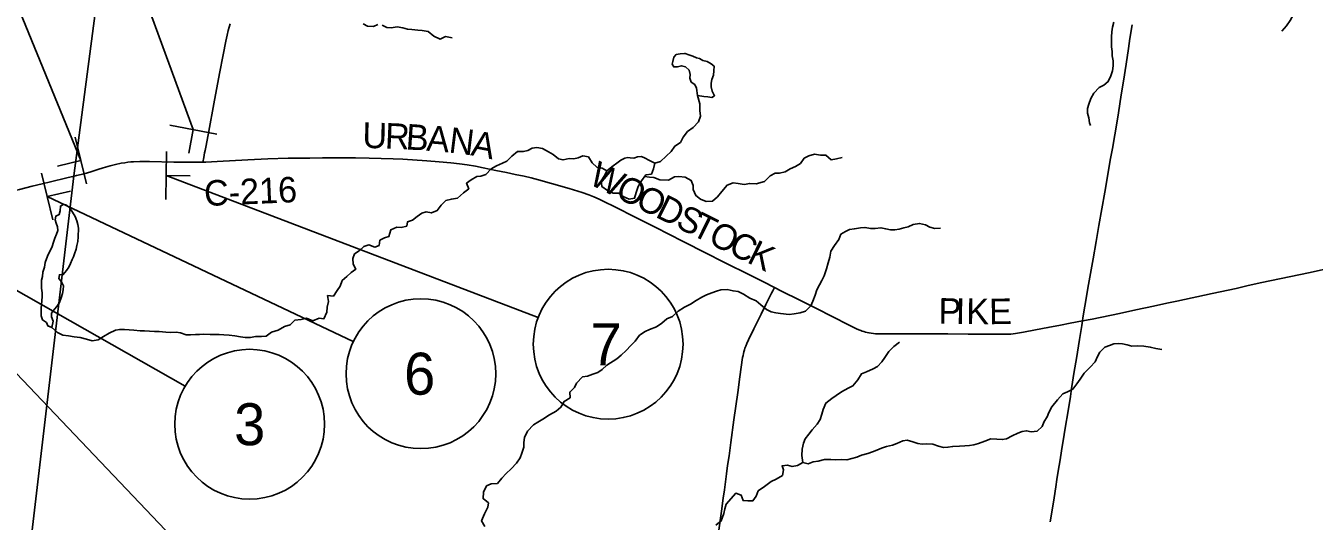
# Model space of a CAD drawing. Extents: x 0 to 1101, y 0 to 440.
# Drawn here: x 356 to 442.1, y 68.6 to 101.7 of the extents above; entities that cross this region are included whole.
import ezdxf

# ---------------------------------------------------------------- set-up
doc = ezdxf.new("R2010")
doc.units = 0
for name, color, linetype in [('Default', 7, 'Continuous'), ('GM_X_County_Road', 7, 'Continuous'), ('GM_X_County_Road_Text', 7, 'Continuous'), ('GM_X_Minor_Lake', 7, 'Continuous'), ('GM_X_Minor_River', 7, 'Continuous'), ('GM_X_State_Location', 7, 'Continuous'), ('GM_X_State_Route', 7, 'Continuous'), ('GM_X_Township', 7, 'Continuous'), ('GM_X_Township_Road', 7, 'Continuous'), ('SH_Masking', 7, 'Continuous'), ('SH_Text', 7, 'Continuous'), ('SN_P_Signs', 7, 'Continuous')]:
    doc.layers.add(name, color=color, linetype=linetype)

msp = doc.modelspace()

# ---------------------------------------------------------------- linework, layer by layer
at = {"layer": 'Default'}
for points in [[(359.263, 91.656), (359.423, 91.693), (359.929, 91.816), (360.377, 91.94), (360.855, 92.095), (361.209, 92.212), (361.673, 92.353), (362.037, 92.443), (362.397, 92.514), (362.644, 92.554), (362.858, 92.582), (363.048, 92.6), (363.239, 92.614), (363.651, 92.629), (364.304, 92.627), (365.926, 92.598), (366.491, 92.587), (367.01, 92.585), (367.558, 92.583), (367.857, 92.588), (367.921, 92.899), (367.983, 93.215), (368.013, 93.362), (368.073, 93.695), (368.259, 94.665), (368.597, 96.479), (368.976, 98.513), (369.211, 99.759), (369.393, 100.674), (369.483, 101.075), (369.562, 101.382), (369.689, 101.824)], [(348.965, 89.153), (349.336, 89.261), (349.645, 89.344), (350.108, 89.45), (350.608, 89.565), (350.951, 89.644), (351.412, 89.756), (352.146, 89.933), (353.305, 90.216), (353.598, 90.289), (354.275, 90.452), (355.059, 90.64), (355.621, 90.771), (356.471, 90.987), (357.142, 91.149), (357.681, 91.279), (358.77, 91.542), (359.263, 91.656)]]:
    msp.add_lwpolyline(points, dxfattribs=at)
at = {"layer": 'GM_X_County_Road'}
for points in [[(426.602, 81.99), (426.628, 82.176), (426.716, 82.735), (426.8, 83.23), (426.967, 84.185), (427.311, 86.131), (427.513, 87.288), (427.701, 88.371), (428.085, 90.594), (428.172, 91.089), (428.459, 92.722), (428.594, 93.511), (428.759, 94.409), (428.891, 95.2), (428.998, 95.882), (429.188, 97.077), (429.332, 97.997), (429.508, 99.139), (429.666, 100.17), (429.772, 100.852), (429.909, 101.754)], [(367.857, 92.588), (368.063, 92.598), (368.82, 92.635), (370.863, 92.744), (372.201, 92.8), (373.56, 92.852), (374.119, 92.856), (375.013, 92.863), (375.852, 92.872), (377.101, 92.881), (378.052, 92.877), (378.965, 92.86), (380.568, 92.818), (381.22, 92.785), (382.82, 92.68), (383.638, 92.617), (384.419, 92.549), (384.994, 92.486), (385.511, 92.411), (386.062, 92.313), (386.574, 92.211), (387.415, 92.042), (388.145, 91.889), (388.71, 91.774), (389.31, 91.644), (389.782, 91.532), (390.269, 91.405), (391.15, 91.163), (392.314, 90.825), (393.189, 90.561), (393.63, 90.406), (393.959, 90.272), (394.319, 90.115), (394.69, 89.942), (395.326, 89.628), (396.824, 88.874), (398.24, 88.162), (398.835, 87.856), (400.064, 87.23), (401.345, 86.584), (402.743, 85.88), (404.355, 85.063), (405.289, 84.599), (406.031, 84.223)], [(426.602, 81.99), (427.25, 82.119), (429.074, 82.497), (430.168, 82.735), (431.334, 82.983), (432.227, 83.174), (432.902, 83.317), (435.27, 83.828), (436.856, 84.166), (437.656, 84.346), (438.584, 84.551), (441.683, 85.208), (443.524, 85.604)], [(406.031, 84.223), (406.503, 83.985), (407.724, 83.385), (408.839, 82.822), (409.889, 82.296), (411.016, 81.718), (411.516, 81.47), (411.668, 81.402), (411.788, 81.353), (411.897, 81.312), (411.997, 81.279), (412.115, 81.244), (412.228, 81.217), (412.353, 81.189), (412.483, 81.168), (412.637, 81.146), (412.777, 81.134), (413.11, 81.12), (414.228, 81.121), (415.029, 81.124), (415.794, 81.13), (417.602, 81.123), (418.962, 81.116), (419.353, 81.113), (420.08, 81.107), (420.788, 81.099), (421.514, 81.102), (421.654, 81.108), (421.819, 81.118), (421.979, 81.132), (422.124, 81.15), (422.655, 81.24), (423.462, 81.39), (424.286, 81.543), (425.128, 81.705), (425.786, 81.835), (426.602, 81.99)], [(424.437, 68.587), (424.589, 69.506), (424.7, 70.187), (424.819, 70.922), (424.896, 71.4), (424.986, 71.971), (425.105, 72.725), (425.202, 73.332), (425.375, 74.418), (425.465, 74.97), (425.611, 75.853), (425.792, 76.937), (425.875, 77.472), (426.053, 78.613), (426.197, 79.477), (426.41, 80.745), (426.56, 81.691), (426.602, 81.99)]]:
    msp.add_lwpolyline(points, dxfattribs=at)
at = {"layer": 'GM_X_Minor_Lake'}
for points in [[(400.066, 99.831), (400.023, 99.843), (399.726, 99.813), (399.464, 99.771), (399.302, 99.591), (399.252, 99.318), (399.204, 99.136), (399.304, 98.941), (399.554, 98.949), (399.817, 99.026), (400.09, 98.954), (400.326, 98.723), (400.401, 98.448), (400.386, 98.198), (400.462, 97.935), (400.711, 97.772), (400.832, 97.52), (400.888, 97.03)], [(400.888, 97.03), (401.326, 96.978), (401.576, 96.94), (401.86, 96.914), (402.033, 97.025), (401.877, 97.323), (401.802, 97.609), (401.794, 97.86), (401.843, 98.11), (401.95, 98.393), (401.988, 98.678), (402.015, 98.985), (401.801, 99.159), (401.541, 99.299), (401.258, 99.382), (401.02, 99.499), (400.827, 99.547), (400.578, 99.653), (400.318, 99.759), (400.066, 99.831)], [(398.05, 92.522), (397.643, 92.721), (397.406, 92.861), (397.145, 92.967), (396.883, 92.948), (396.643, 92.86), (396.404, 92.886), (396.233, 92.899), (396.039, 92.856), (395.764, 92.712), (395.499, 92.511), (395.269, 92.343), (394.842, 92.007)], [(394.842, 92.007), (394.713, 91.712), (394.457, 91.351), (394.509, 90.963), (394.881, 90.707), (395.254, 90.52), (395.641, 90.526), (395.934, 90.306), (396.319, 90.13), (396.696, 90.182), (396.792, 90.556), (396.935, 90.965), (397.145, 91.349), (397.447, 91.744), (397.812, 91.784), (397.965, 92.136), (398.05, 92.522)], [(357.769, 81.562), (357.866, 81.982), (357.745, 82.257), (357.76, 82.519), (357.957, 82.767), (358.119, 82.947), (358.294, 83.218), (358.401, 83.536), (358.484, 83.819), (358.545, 84.069), (358.549, 84.331), (358.427, 84.595), (358.237, 84.825), (358.286, 85.075), (358.537, 85.083), (358.746, 85.365), (358.908, 85.591), (359.014, 85.817), (359.143, 86.089), (359.226, 86.281), (359.285, 86.474), (359.392, 86.78), (359.453, 87.018), (359.514, 87.302), (359.541, 87.598), (359.549, 88.19), (359.518, 88.419), (359.453, 88.67), (359.344, 88.956), (359.154, 89.255), (358.954, 89.554), (358.717, 89.751), (358.535, 89.765), (358.351, 89.654), (358.336, 89.346), (358.264, 89.085), (358.144, 89.034)], [(358.144, 89.034), (358.034, 88.986), (357.997, 88.747), (358.062, 88.519), (358.161, 88.267), (358.18, 88.027), (358.097, 87.778), (357.968, 87.506), (357.896, 87.256), (357.8, 86.962), (357.671, 86.667), (357.542, 86.418), (357.424, 86.147), (357.329, 85.886), (357.28, 85.59), (357.184, 85.25), (357.145, 84.966), (357.096, 84.704), (357.089, 84.169), (357.141, 83.872), (357.138, 83.622), (357.111, 83.337), (357.096, 83.087), (357.07, 82.848), (357.055, 82.609), (357.074, 82.335), (357.149, 82.061), (357.42, 81.897), (357.52, 81.657), (357.769, 81.562)]]:
    msp.add_lwpolyline(points, dxfattribs=at)
at = {"layer": 'GM_X_Minor_River'}
for points in [[(441.413, 103.145), (441.069, 102.842), (440.699, 102.437), (440.477, 102.053), (440.221, 101.681), (439.92, 101.343)], [(378.559, 101.817), (378.853, 101.665), (379.263, 101.636), (379.549, 101.769)], [(379.845, 101.742), (380.15, 101.567), (380.435, 101.564), (380.834, 101.615), (381.209, 101.553), (381.527, 101.469), (381.823, 101.454), (382.22, 101.403), (382.516, 101.376), (382.914, 101.303), (383.285, 100.99), (383.715, 100.802), (384.071, 100.968), (384.502, 100.894)], [(428.704, 101.929), (428.599, 101.61), (428.561, 101.29), (428.535, 100.947), (428.544, 100.581), (428.541, 100.284), (428.573, 99.986), (428.581, 99.689), (428.647, 99.345), (428.655, 99.025), (428.607, 98.682), (428.501, 98.34), (428.315, 97.965), (428.027, 97.727), (427.717, 97.57), (427.36, 97.185), (427.162, 96.844), (427.022, 96.468), (426.939, 96.16), (426.937, 95.862), (427.025, 95.541)], [(388.501, 92.992), (388.881, 93.306), (389.269, 93.301), (389.554, 93.365), (389.841, 93.521), (390.172, 93.562), (390.547, 93.511), (390.942, 93.278), (391.247, 93.092), (391.619, 92.813), (391.914, 92.741), (392.326, 92.827), (392.633, 92.8), (392.919, 92.876), (393.239, 93.008), (393.603, 92.935), (393.848, 92.533), (394.162, 92.255), (394.526, 92.182), (394.842, 92.007), (394.713, 91.712), (394.457, 91.351), (394.509, 90.963), (394.881, 90.707), (395.254, 90.52), (395.641, 90.526), (395.934, 90.306), (396.319, 90.13), (396.696, 90.182), (396.792, 90.556), (396.935, 90.965), (397.145, 91.349), (397.447, 91.744), (397.812, 91.784), (397.965, 92.136), (398.05, 92.522), (398.416, 92.642), (398.808, 92.979), (399.132, 93.293), (399.376, 93.666), (399.756, 93.911), (399.932, 94.262), (400.233, 94.646), (400.613, 94.902), (400.96, 95.285), (401.102, 95.659), (401.05, 96.047), (401.057, 96.48), (400.888, 97.03)], [(427.025, 95.541), (427.079, 95.221), (427.146, 95.037)], [(357.769, 81.562), (358.151, 81.215), (358.513, 81.039), (358.888, 80.988), (359.275, 80.937), (359.672, 80.886), (360.092, 80.766), (360.466, 80.659), (360.866, 80.722), (361.222, 80.956), (361.601, 81.167), (362.025, 81.366), (362.311, 81.431), (362.63, 81.426), (362.937, 81.399), (363.244, 81.372), (363.665, 81.332), (363.972, 81.328), (364.302, 81.312), (364.644, 81.296), (364.94, 81.292), (365.395, 81.24), (365.691, 81.225), (366.089, 81.231), (366.374, 81.204), (366.748, 81.074), (367.032, 81.058), (367.363, 81.077), (367.648, 81.095), (367.933, 81.103), (368.342, 81.086), (368.673, 81.093), (368.957, 81.078), (369.253, 81.062), (369.629, 81.034), (370.004, 80.995), (370.367, 80.933), (370.686, 80.883), (371.039, 80.89), (371.381, 80.953), (371.78, 80.948), (372.088, 80.966), (372.445, 81.246), (372.891, 81.366), (373.316, 81.611), (373.682, 81.742), (374.005, 82.034), (374.416, 82.097), (374.793, 82.183), (375.212, 82.006), (375.624, 82.172), (375.943, 82.133), (376.131, 82.575), (376.159, 82.905), (376.244, 83.28), (376.193, 83.679), (376.579, 83.651), (376.824, 84.013), (377.022, 84.306), (377.164, 84.68), (377.475, 84.949), (377.775, 85.219), (378.074, 85.443), (377.908, 85.787), (377.879, 86.152), (377.986, 86.469), (378.308, 86.67), (378.608, 86.962), (378.952, 87.06), (379.348, 86.918), (379.634, 87.028), (379.685, 87.38), (379.983, 87.536), (380.292, 87.634), (380.412, 88.066), (380.825, 88.254), (381.11, 88.239), (381.475, 88.325), (381.536, 88.609), (381.857, 88.707), (382.168, 88.965), (382.479, 89.188), (382.764, 89.276), (383.128, 89.202), (383.517, 89.357), (383.784, 89.718), (384.097, 90.032), (384.462, 90.13), (384.873, 90.193), (385.277, 90.541), (385.622, 90.809), (385.468, 91.176), (385.768, 91.4), (386.147, 91.634), (386.432, 91.664), (386.764, 91.774), (387.111, 92.134), (387.478, 92.345), (387.868, 92.522), (388.166, 92.655), (388.501, 92.992)], [(397.354, 91.622), (397.695, 91.581), (397.98, 91.566), (398.376, 91.401), (398.957, 91.393), (399.359, 91.615), (399.644, 91.634), (400.076, 91.583), (400.471, 91.373), (400.603, 91.04), (400.61, 90.755), (400.776, 90.354), (401.103, 90.122), (401.476, 89.958), (401.886, 89.975), (402.221, 90.267), (402.511, 90.639), (402.87, 91.044), (403.271, 91.209), (403.6, 91.171), (404.01, 91.108), (404.386, 91.172), (404.807, 91.143), (405.368, 91.295), (405.749, 91.666), (406.082, 91.855), (406.378, 91.862), (406.744, 91.949), (407.077, 92.149), (407.432, 92.293), (407.765, 92.493), (408.021, 92.854), (408.319, 93.01), (408.697, 93.13), (409.095, 93.056), (409.47, 93.051), (409.808, 92.739), (410.184, 92.814), (410.562, 92.9)], [(404.38, 83.515), (404.81, 83.327), (405.125, 83.06), (405.496, 82.759), (405.813, 82.606), (406.131, 82.522), (406.426, 82.484), (407.018, 82.431), (407.349, 82.472), (407.748, 82.535), (408.114, 82.644), (408.45, 83.004), (408.591, 83.321), (408.745, 83.718), (408.852, 84.069), (409.028, 84.398), (409.203, 84.691), (409.355, 84.997), (409.499, 85.462), (409.618, 85.86), (409.726, 86.257), (409.8, 86.655), (410.034, 87.028), (410.335, 87.434), (410.466, 87.774), (410.764, 87.963), (411.051, 88.085), (411.371, 88.149), (411.77, 88.212), (412.067, 88.231), (412.464, 88.157), (412.749, 88.153), (413.137, 88.216), (413.466, 88.132), (413.773, 88.082), (414.08, 88.078), (414.366, 88.12), (414.674, 88.195), (414.96, 88.283), (415.304, 88.426), (415.727, 88.5), (416.113, 88.415), (416.406, 88.252), (416.736, 88.167), (417.123, 88.185)], [(386.701, 68.268), (386.479, 68.658), (386.679, 69.111), (386.891, 69.564), (386.929, 69.849), (386.569, 70.139), (386.609, 70.56), (386.809, 70.979), (387.118, 71.111), (387.528, 71.14), (387.83, 71.5), (388.107, 71.816), (388.442, 72.119), (388.8, 72.49), (389.056, 72.851), (389.163, 73.157), (389.294, 73.577), (389.299, 73.873), (389.349, 74.215), (389.549, 74.645), (389.942, 75.061), (390.24, 75.228), (390.574, 75.429), (391.011, 75.73), (391.447, 75.964), (391.77, 76.233), (391.98, 76.618), (392.394, 76.863), (392.365, 77.239), (392.677, 77.543), (392.818, 77.837), (393.222, 78.253), (393.542, 78.306), (393.908, 78.449), (394.229, 78.559), (394.528, 78.76), (394.839, 79.029), (395.495, 79.453), (395.806, 79.711), (396.129, 80.026), (396.43, 80.352), (396.719, 80.644), (397.021, 81.039), (397.4, 81.296), (397.687, 81.429), (398.145, 81.605), (398.513, 81.839), (398.836, 82.131), (399.225, 82.297), (399.595, 82.634), (400.02, 82.901), (400.433, 83.112), (400.801, 83.347), (401.18, 83.581), (401.501, 83.725), (401.856, 83.868), (402.165, 83.989), (402.451, 84.076), (402.884, 84.082), (403.27, 83.997), (403.6, 83.958), (403.973, 83.782), (404.38, 83.515)], [(402.125, 68.366), (402.482, 68.646), (402.648, 69.146), (402.709, 69.441), (402.805, 69.759), (403.454, 70.502), (403.816, 70.372), (403.936, 70.006), (404.244, 69.99), (404.597, 69.985), (404.817, 70.29), (404.948, 70.642), (405.362, 70.932), (405.811, 71.279), (406.155, 71.423), (406.568, 71.679), (406.642, 72.043), (406.544, 72.329), (406.908, 72.359), (407.215, 72.286), (407.569, 72.338), (407.936, 72.55), (408.288, 72.454), (408.62, 72.597), (408.951, 72.638), (409.374, 72.735), (409.795, 72.741), (410.091, 72.726), (410.502, 72.743), (410.855, 72.727), (411.209, 72.813), (411.54, 72.9), (411.85, 73.032), (412.262, 73.152), (412.582, 73.262), (412.868, 73.36), (413.178, 73.504), (413.509, 73.602), (413.91, 73.699), (414.196, 73.821), (414.597, 73.986), (414.882, 74.028), (415.279, 73.92), (415.608, 73.813), (415.904, 73.764), (416.189, 73.782), (416.598, 73.765), (416.984, 73.635), (417.313, 73.551), (417.609, 73.558), (417.94, 73.622), (418.396, 73.639), (418.749, 73.645), (419.046, 73.687), (419.343, 73.728), (419.652, 73.804), (420.075, 73.958), (420.476, 74.123), (420.874, 74.095), (421.238, 74.067), (421.524, 74.132), (421.914, 74.32), (422.292, 74.497), (422.579, 74.607), (422.864, 74.66), (423.182, 74.599), (423.57, 74.64), (423.905, 74.954), (424.035, 75.271), (424.244, 75.588), (424.362, 75.882), (424.55, 76.267), (424.921, 76.729), (425.28, 77.135), (425.589, 77.256), (425.945, 77.433), (426.223, 77.783), (426.444, 78.099), (426.723, 78.505), (427.105, 78.899), (427.452, 79.259), (427.593, 79.61), (427.757, 79.904), (428.103, 80.23), (428.401, 80.363), (428.687, 80.462), (428.984, 80.492)], [(407.931, 72.547), (407.852, 73.007), (407.881, 73.439), (407.966, 73.826), (408.084, 74.132), (408.316, 74.436), (408.56, 74.729), (408.872, 75.101), (409.082, 75.406), (409.201, 75.769), (409.285, 76.087), (409.462, 76.506), (409.854, 76.82), (410.153, 77.01), (410.509, 77.267), (410.946, 77.512), (411.267, 77.667), (411.602, 78.05), (411.848, 78.468), (412.18, 78.589), (412.615, 78.799), (412.902, 78.955), (413.192, 79.259), (413.401, 79.552), (413.669, 79.959), (414.003, 80.285), (414.372, 80.565)], [(428.984, 80.492), (429.268, 80.465), (429.575, 80.393), (429.904, 80.297), (430.292, 80.326), (430.701, 80.298), (431.122, 80.246), (431.497, 80.161), (431.894, 80.076)]]:
    msp.add_lwpolyline(points, dxfattribs=at)
at = {"layer": 'GM_X_State_Route'}
for points in [[(359.263, 91.656), (359.423, 91.693), (359.929, 91.816), (360.377, 91.94), (360.855, 92.095), (361.209, 92.212), (361.673, 92.353), (362.037, 92.443), (362.397, 92.514), (362.644, 92.554), (362.858, 92.582), (363.048, 92.6), (363.239, 92.614), (363.651, 92.629), (364.304, 92.627), (365.926, 92.598), (366.491, 92.587), (367.01, 92.585), (367.558, 92.583), (367.857, 92.588), (367.921, 92.899), (367.983, 93.215), (368.013, 93.362), (368.073, 93.695), (368.259, 94.665), (368.597, 96.479), (368.976, 98.513), (369.211, 99.759), (369.393, 100.674), (369.483, 101.075), (369.562, 101.382), (369.689, 101.824)], [(348.965, 89.153), (349.336, 89.261), (349.645, 89.344), (350.108, 89.45), (350.608, 89.565), (350.951, 89.644), (351.412, 89.756), (352.146, 89.933), (353.305, 90.216), (353.598, 90.289), (354.275, 90.452), (355.059, 90.64), (355.621, 90.771), (356.471, 90.987), (357.142, 91.149), (357.681, 91.279), (358.77, 91.542), (359.263, 91.656)]]:
    msp.add_lwpolyline(points, dxfattribs=at)
at = {"layer": 'GM_X_Township'}
for points in [[(456.87, 41.812), (429.195, 44.697), (407.625, 46.582), (393.244, 47.835), (358.093, 49.313), (354.24, 49.634), (354.518, 51.702), (355.546, 60.287), (359.256, 91.672), (367.226, 152.429), (371.877, 189.376), (373.469, 201.961), (373.82, 204.757), (378.028, 238.099), (380.197, 255.256), (380.697, 259.316), (380.797, 261.323), (386.092, 260.749), (411.56, 258.243), (435.213, 255.629), (445.064, 254.562)], [(371.877, 189.376), (367.226, 152.429), (359.256, 91.672), (355.546, 60.287)]]:
    msp.add_lwpolyline(points, dxfattribs=at)
at = {"layer": 'GM_X_Township_Road'}
msp.add_lwpolyline([(402.281, 67.716), (402.488, 69.287), (402.607, 70.155), (402.686, 70.708), (402.831, 71.795), (402.903, 72.35), (402.998, 72.995), (403.114, 73.882), (403.322, 75.396), (403.581, 77.205), (403.727, 78.257), (403.814, 78.903), (403.907, 79.549), (403.932, 79.685), (403.961, 79.824), (403.987, 79.939), (404.025, 80.059), (404.064, 80.174), (404.114, 80.305), (404.184, 80.479), (404.304, 80.732), (404.654, 81.454), (404.851, 81.855), (405.142, 82.438), (405.462, 83.09), (405.838, 83.841), (405.922, 84.007), (406.031, 84.223)], dxfattribs=at)
at = {"layer": 'SH_Masking'}
for centre in [(394.927, 80.439), (382.422, 78.469), (370.987, 75.097)]:
    msp.add_circle(centre, 5, dxfattribs=at)
at = {"layer": 'SH_Text'}
for p, q in [((350.506, 115.21), (359.718, 92.696)), ((363.384, 105.246), (367.221, 94.762)), ((365.413, 91.695), (390.256, 82.221)), ((357.461, 90.288), (377.903, 80.609)), ((350.554, 86.784), (366.675, 77.63)), ((351.269, 82.814), (367.535, 65.768))]:
    msp.add_line(p, q, dxfattribs=at)
for centre in [(394.927, 80.439), (382.422, 78.469), (370.987, 75.097)]:
    msp.add_circle(centre, 5, dxfattribs=at)
at = {"layer": 'SN_P_Signs'}
for p, q in [((368.792, 94.46), (365.649, 95.063)), ((367.221, 94.762), (366.919, 93.19)), ((360.091, 91.14), (359.345, 94.252)), ((365.384, 90.096), (365.442, 93.295)), ((359.718, 92.696), (358.162, 92.323)), ((357.834, 88.732), (357.088, 91.844)), ((365.413, 91.695), (367.012, 91.666)), ((357.461, 90.288), (359.017, 90.661))]:
    msp.add_line(p, q, dxfattribs=at)

# ---------------------------------------------------------------- texts
at = {"layer": 'GM_X_County_Road_Text'}
for s, height, rotation, p in [('U', 1.705, 358.57493, (378.501, 93.542)), ('R', 1.705, 357.55492, (379.997, 93.504)), ('B', 1.705, 356.26711, (381.375, 93.446)), ('A', 1.705, 355.48801, (382.755, 93.356)), ('N', 1.705, 352.90497, (384.235, 93.239)), ('A', 1.705, 349.19903, (385.699, 93.058)), ('W', 1.705, 333.59085, (393.549, 91.175)), ('C-216', 1.7045, 2.46127, (367.98, 89.657)), ('O', 1.705, 333.58972, (395.318, 90.296)), ('O', 1.705, 333.58972, (396.662, 89.629)), ('D', 1.705, 333.59058, (398.005, 88.962)), ('S', 1.705, 333.59126, (399.349, 88.295)), ('T', 1.705, 333.59211, (400.379, 87.783)), ('O', 1.705, 333.58972, (401.521, 87.216)), ('C', 1.705, 333.59154, (402.864, 86.549)), ('K', 1.705, 333.77536, (404.123, 85.924)), ('P', 1.705, 359.24928, (416.977, 81.813)), ('I', 1.705, 359.24942, (418.127, 81.798)), ('K', 1.705, 359.32517, (418.829, 81.789)), ('E', 1.705, 0.66805, (420.372, 81.772))]:
    msp.add_text(s, height=height, rotation=rotation, dxfattribs=at).set_placement(p)
at = {"layer": 'GM_X_State_Location'}
for s in ['s', 'r']:
    msp.add_text(s, height=0.00568, dxfattribs=at).set_placement((368.799, 96.79))
at = {"layer": 'SH_Text'}
for s, p in [('7', (393.746, 79.039)), ('6', (381.299, 77.069)), ('3', (369.95, 73.697))]:
    msp.add_text(s, height=2.8, rotation=360, dxfattribs=at).set_placement(p)

doc.saveas('drawing.dxf')
